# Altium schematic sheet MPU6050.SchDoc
size A; SheetNumber: 4; SheetTotal: 4
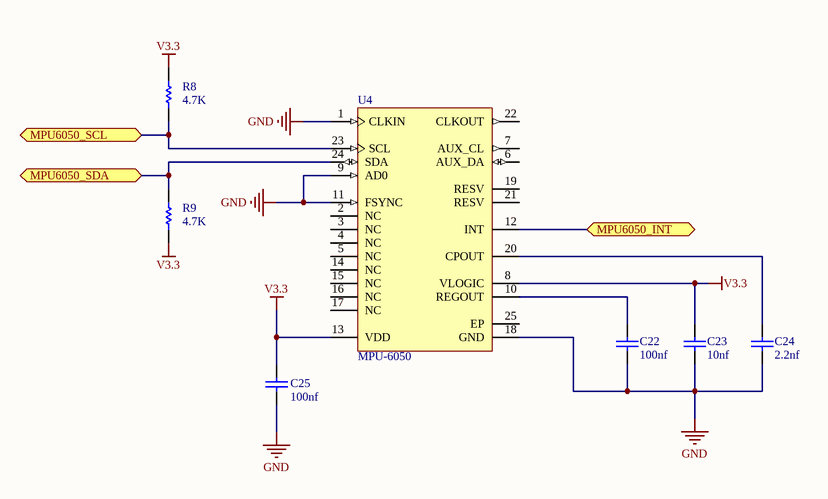
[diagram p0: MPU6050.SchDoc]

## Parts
C22  value 100nf  [CAPC1206(3216)190_N]  (hidden comment: CAP 1206)
C23  value 10nf  [CAPC1206(3216)190_N]  (hidden comment: CAP 1206)
C24  value 2.2nf  [CAPC1206(3216)190_N]  (hidden comment: CAP 1206)
C25  value 100nf  [CAPC1206(3216)190_N]  (hidden comment: CAP 1206)
R8  value 4.7K  [RESC3216X70X50NL05T20]  (hidden comment: ERJ-8GEY0R00V)
R9  value 4.7K  [RESC3216X70X50NL05T20]  (hidden comment: ERJ-8GEY0R00V)
U4  MPU-6050  [IS-QFN-24_V]

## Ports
MPU6050_INT (bidir, see Microcontroller[4B]), MPU6050_SCL (bidir, see Microcontroller[4B]), MPU6050_SDA (bidir, see Microcontroller[4B])

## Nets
GND: C22.2 C23.1 C24.1 C25.1 U4.1(CLKIN) U4.9(AD0) U4.11(FSYNC) U4.18(GND)
V3.3: C23.2 C25.2 R8.2 R9.1 U4.8(VLOGIC) U4.13(VDD)
MPU6050_INT: U4.12(INT) ; port MPU6050_INT
MPU6050_SCL: R8.1 U4.23(SCL) ; port MPU6050_SCL
MPU6050_SDA: R9.2 U4.24(SDA) ; port MPU6050_SDA
NetC22_1: C22.1 U4.10(REGOUT)
NetC24_2: C24.2 U4.20(CPOUT)

Not connected (* = marked no-connect by the designer): U4 2(NC) 3(NC) 4(NC) 5(NC) 6(AUX_DA) 7(AUX_CL) 14(NC) 15(NC) 16(NC) 17(NC) 19(RESV) 21(RESV) 22(CLKOUT) 25(EP)

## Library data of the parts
C22-C25 = CMP-1037-04961-1: Tolerance: Â±10%; Case-EIA: 1206; Case-Metric: 3216; Rated Voltage: 6.3 V
R8 R9 = CMP-2003-00541-1: Manufacturer: Panasonic
U4 = CMP-1753-00002-2: 3-Axis Gyroscope, Accelerometer and a Digital Motion Processor(TM) (DMP), 2.375 to 3.46 V, -40 to 85 degC, 24-Pin QFN, RoHS, Tape and Reel; Manufacturer: InvenSense; Featured Product: MPU-60506-Axis,IntegratedI²CSolution; Other Names: 1428-1007-2 / MPU6050; Sensor Type: MotionTracking; Online Catalog: MPU-6000™Series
